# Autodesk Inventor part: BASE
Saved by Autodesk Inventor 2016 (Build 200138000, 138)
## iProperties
Created: 2013-10
Part Number: BASE
Material: solidworks materials|ABS
Document SubType Name: Modeling
Designer: Bruno
Density: 1.02 g/cm^3
Appearance: 202,209,238
Author: Bruno
Sending System: SolidWorks 2013
Last Author: christophe
Last Saved: 2014-02-15
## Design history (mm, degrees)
feature "Congé4"
node "Solide1"
